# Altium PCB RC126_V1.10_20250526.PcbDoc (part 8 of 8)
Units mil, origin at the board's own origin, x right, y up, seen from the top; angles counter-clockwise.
Board outline 6299.62 x 3544.12 mil, 4 copper layers (Top, GND, Power, Bottom), stack 35.4 mil thick; 509 components, 417 nets, 1867 pads, 2150 vias.
Unrouted connection lines stored in the file: 1451.
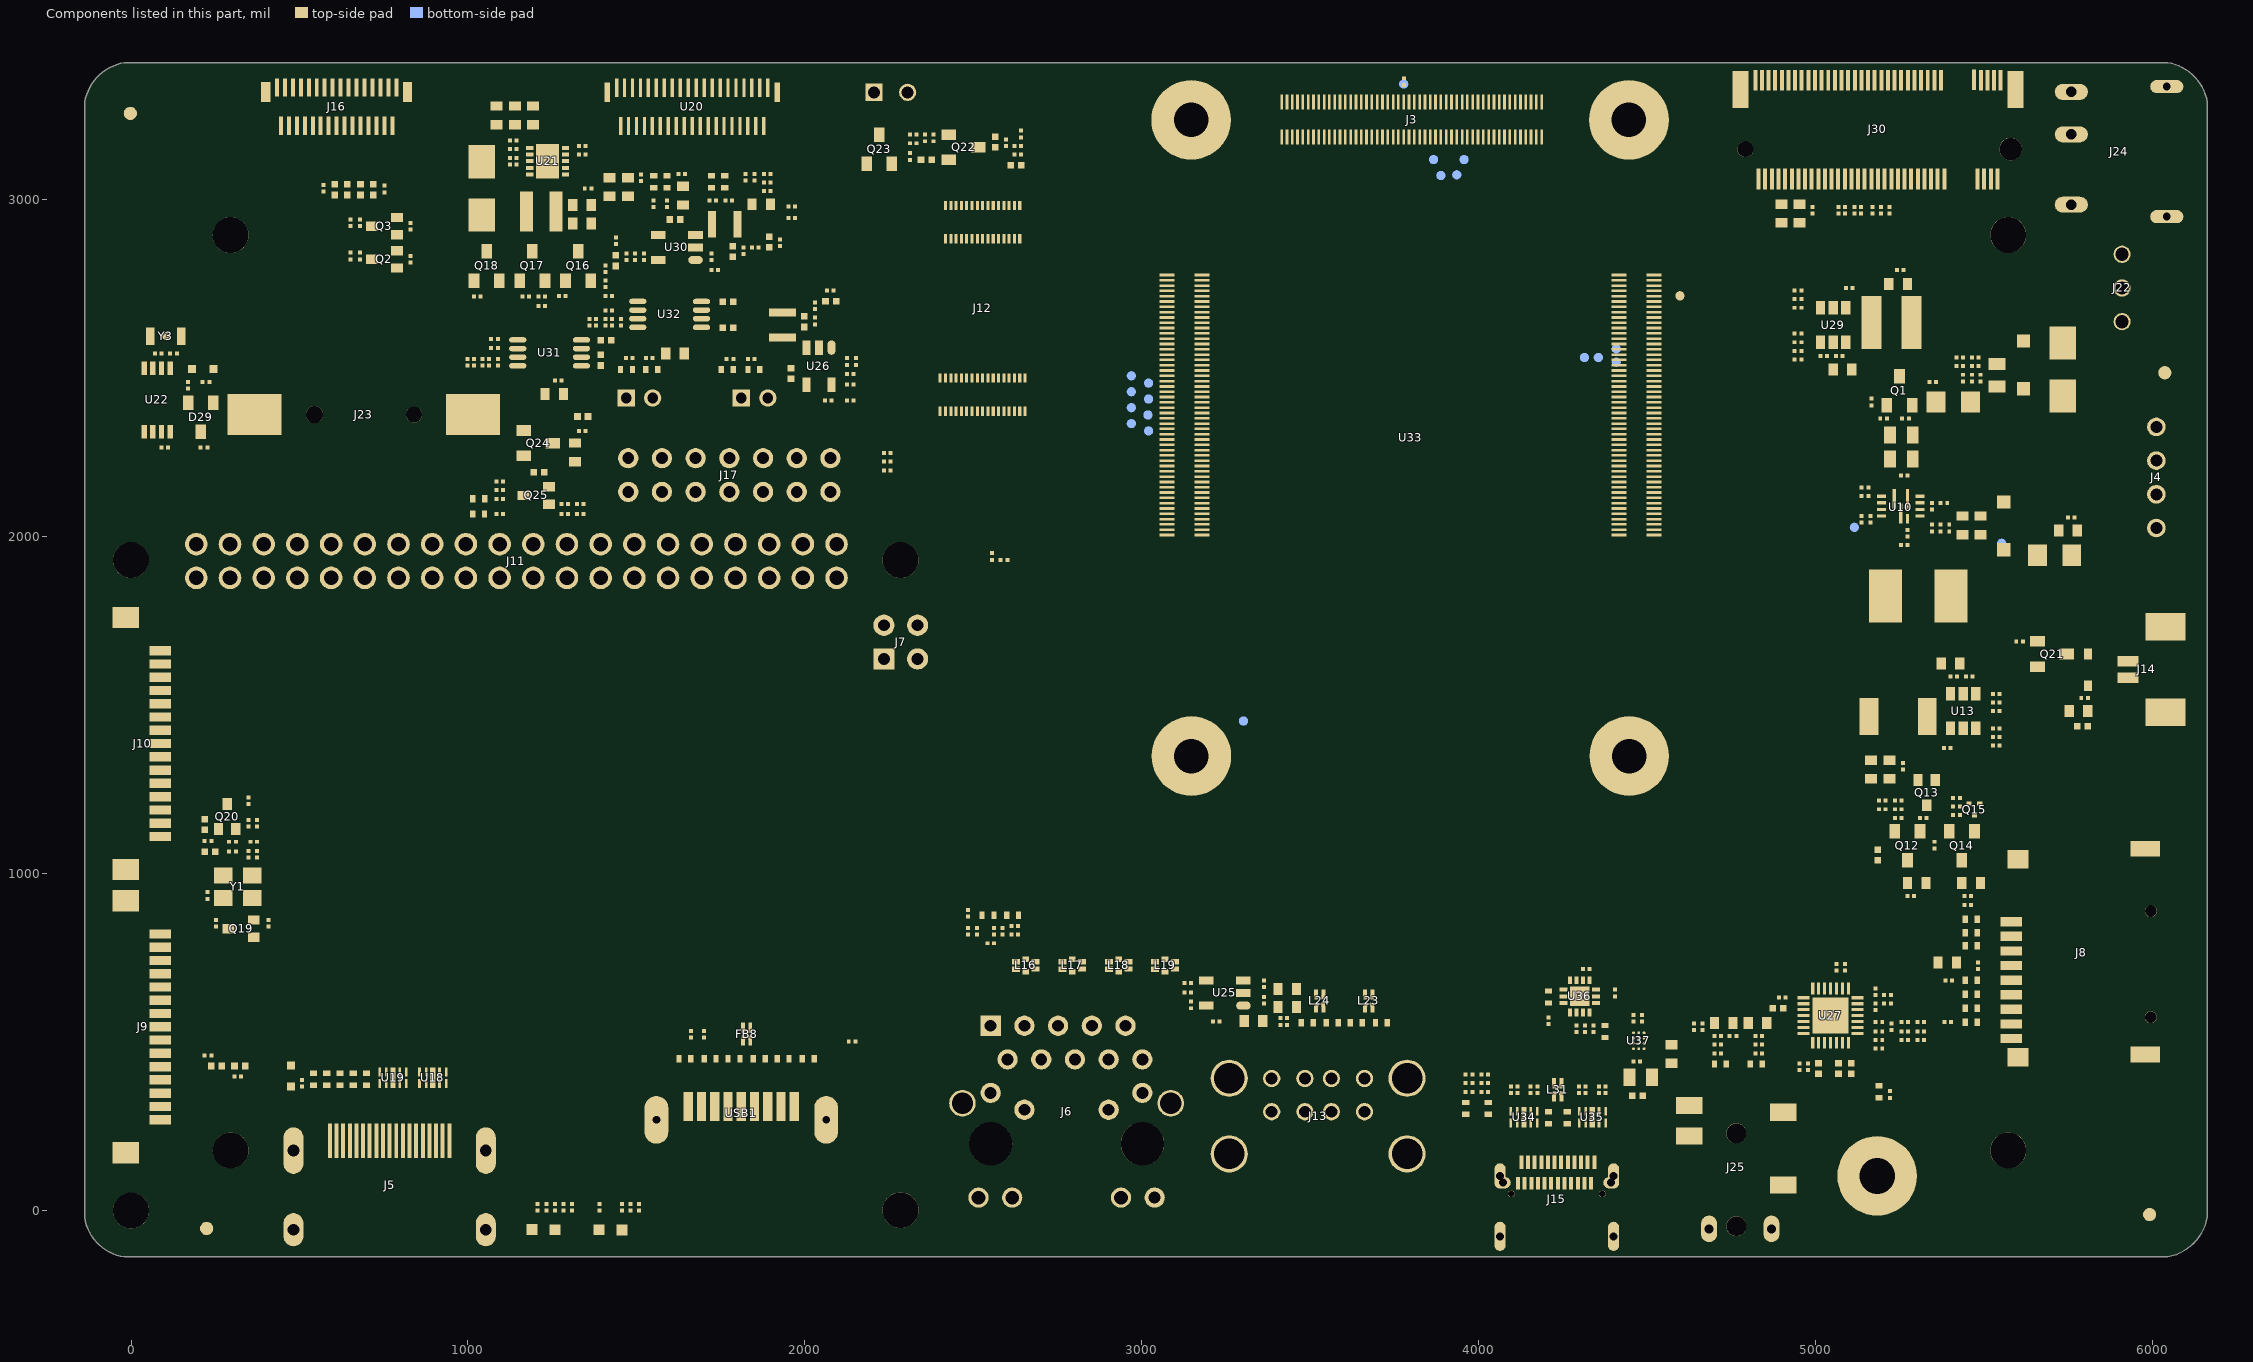
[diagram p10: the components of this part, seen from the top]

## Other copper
Top:
  region net VCC5V: 5732.28,1911.42 6039.37,1911.42 6039.37,2064.96 5761.81,2064.96 5761.81,2007.87 5732.28,1978.35 5732.28,1911.42
  region net +5V_INPUT: 4547.24,2685.04 4547.24,2600.39 4665.35,2600.39 4665.35,2685.04 4547.24,2685.04
  region net 5V_USB_HOST: 3417.32,586.61 3417.32,677.17 3379.92,677.17 3379.92,586.61 3417.32,586.61
  region net N37314100: 2039.37,2643.7 2039.37,2681.1 1889.76,2681.1 1889.76,2643.7 2039.37,2643.7
  region net VCC_UFS1V2_S0_P: 1848.43,2852.36 1848.43,2883.86 1816.93,2883.86 1816.93,2966.54 1775.59,2966.54 1775.59,2852.36 1848.43,2852.36
  region net +5V_INPUT: 1421.26,2948.82 1350.39,2948.82 1350.39,2909.45 1395.67,2909.45 1421.26,2935.04 1421.26,2948.82
  region net VCC12V: 6039.37,2354.33 5391.73,2354.33 5385.83,2360.24 5385.83,2431.1 5269.68,2431.1 5269.68,2269.69 6039.37,2269.69 6039.37,2354.33
  region net +5V_INPUT: 5685.04,1891.73 5685.04,2021.65 5338.58,2021.65 5338.58,1744.09 5456.69,1744.09 5456.69,1879.92 5468.5,1891.73 5685.04,1891.73
  region net N38162991: 5667.32,2712.6 5667.32,2525.59 5793.31,2525.59 5793.31,2712.6 5667.32,2712.6
  region net N19463943: 5074.8,2553.15 5194.88,2553.15 5196.85,2555.12 5196.85,2718.5 5127.95,2718.5 5127.95,2616.14 5114.17,2602.36 5074.8,2602.36 5074.8,2553.15
  region net +5V_INPUT: 1608.27,2950.79 1543.31,2950.79 1543.31,2883.86 1608.27,2883.86 1608.27,2950.79
  region net +5V_INPUT: 1124.02,2236.22 1124.02,2181.1 1204.72,2181.1 1204.72,2255.91 1143.7,2255.91 1124.02,2236.22
  region net VBUS_TYPEC0: 4413.39,411.42 4462.6,411.42 4462.6,466.54 4444.88,466.54 4444.88,515.75 4413.39,515.75 4413.39,411.42
  region net 5V_S0: 1230.32,2261.81 1334.65,2261.81 1334.65,2366.14 1230.32,2366.14 1230.32,2261.81
  region net N38162991: 5706.69,3372.05 5706.69,3273.62 5952.76,3273.62 5952.76,3372.05 5706.69,3372.05
  region net 5V_USB_HOST: 3417.32,562.99 3342.52,562.99 3342.52,263.78 3417.32,263.78 3417.32,562.99
  region net N19591855: 1001.97,2903.54 1192.91,2903.54 1192.91,3098.43 1169.29,3098.43 1131.89,3061.02 1131.89,3013.78 1124.02,3005.91 1001.97,3005.91 1001.97,2903.54
  region net 5V_USB_HOST: 3279.53,620.08 3279.53,588.58 3326.77,588.58 3342.52,572.83 3342.52,559.06 3417.32,559.06 3417.32,620.08 3279.53,620.08
  region net +5V_INPUT: 4312.99,570.87 4281.5,570.87 4263.78,553.15 4263.78,543.31 4320.87,543.31 4320.87,562.99 4312.99,570.87
  region net 5V_USB_HOST: 1679.13,352.36 1679.13,194.88 1706.69,194.88 1706.69,352.36 1679.13,352.36
  region net VBUS_TYPEC0: 4464.57,442.91 4413.39,442.91 4413.39,232.28 4464.57,232.28 4464.57,442.91
  region net N37314098: 1891.73,2602.36 1891.73,2578.74 1952.76,2578.74 1992.13,2539.37 2015.75,2539.37 2015.75,2582.68 1996.06,2602.36 1891.73,2602.36
  region net N38162882: 5413.39,1513.78 5413.39,1559.06 5322.83,1559.06 5301.18,1537.4 5301.18,1403.54 5364.17,1403.54 5364.17,1505.91 5372.05,1513.78 5413.39,1513.78
  region net +5V_INPUT: 1948.82,2480.32 1948.82,2419.29 2015.75,2419.29 2015.75,2480.32 1948.82,2480.32
  region net VCC3V3_SYS: 1080.71,1608.27 1080.71,1574.8 1120.08,1574.8 1120.08,1608.27 1080.71,1608.27
  region net +5V_INPUT: 4598.43,401.57 4645.67,401.57 4651.57,407.48 4651.57,515.75 4503.94,515.75 4503.94,476.38 4525.59,476.38 4535.43,466.54 4588.58,466.54 4598.43,456.69 4598.43,401.57
  region net N38163182: 5246.06,2098.43 5246.06,2059.06 5155.51,1968.5 5155.51,1744.09 5257.87,1744.09 5257.87,2098.43 5246.06,2098.43
  region net VCC12V: 5283.46,2082.68 5283.46,2127.95 5291.34,2135.83 5366.14,2135.83 5377.95,2147.64 5377.95,2350.39 5285.43,2350.39 5265.75,2330.71 5265.75,2082.68 5283.46,2082.68
  region net 3V3_PCIE: 5533.46,3108.27 5533.46,3015.75 5586.61,3015.75 5586.61,3108.27 5533.46,3108.27
  region net VCC3V3_SYS: 5362.2,1322.83 5362.2,1370.08 5196.85,1370.08 5187.01,1379.92 5187.01,1523.62 5122.05,1523.62 5122.05,1328.74 5127.95,1322.83 5362.2,1322.83
  region net 3V3_PCIE: 5037.4,3021.65 4820.87,3021.65 4820.87,2976.38 4824.8,2972.44 5037.4,2972.44 5037.4,3021.65
  region net VCC_UFS_S0: 2023.62,2688.98 2070.87,2688.98 2070.87,2736.22 2023.62,2736.22 2023.62,2688.98
  region net +5V_INPUT: 3137.8,606.3 3137.8,553.15 3216.54,553.15 3216.54,622.05 3179.13,622.05 3163.39,606.3 3137.8,606.3
  region net N37314178: 1651.57,2881.89 1734.25,2881.89 1738.19,2885.83 1738.19,2968.5 1700.79,2968.5 1700.79,2921.26 1688.98,2909.45 1651.57,2909.45 1651.57,2881.89
  region net +5V_INPUT: 4568.9,362.2 4476.38,362.2 4476.38,318.9 4568.9,318.9 4568.9,362.2
  region net VCC1V2_UFS_VCCQ_S0: 1856.3,2868.11 1856.3,2848.43 1952.76,2848.43 1952.76,2868.11 1856.3,2868.11
  region net LCD_3V3: 1194.88,2866.14 1194.88,2856.3 1185.04,2856.3 1185.04,2828.74 1228.35,2828.74 1246.06,2846.46 1246.06,2858.27 1238.19,2866.14 1194.88,2866.14
  region net 3V3_PCIE: 5253.94,2557.09 5326.77,2557.09 5326.77,2801.18 5253.94,2801.18 5253.94,2557.09
  region net VCC12V_DCIN: 5429.13,2466.54 5429.13,2368.11 5787.4,2368.11 5787.4,2466.54 5429.13,2466.54
  region net VCC3V3_SYS: 350.39,1649.61 350.39,1624.02 389.76,1624.02 389.76,1649.61 350.39,1649.61
  region net +5V_INPUT: 5037.4,2596.46 5037.4,2551.18 5027.56,2541.34 5027.56,2525.59 5021.65,2519.69 4978.35,2519.69 4978.35,2462.6 5064.96,2462.6 5064.96,2596.46 5037.4,2596.46
  region net N19591849: 1324.8,3029.53 1240.16,3029.53 1240.16,2903.54 1324.8,2903.54 1324.8,3029.53
  region net 5V_S0: 1216.54,2181.1 1285.43,2181.1 1285.43,2366.14 1216.54,2366.14 1216.54,2181.1
  region net N19591849: 1324.8,2996.06 1324.8,3003.94 1332.68,3011.81 1352.36,3011.81 1352.36,3076.77 1330.71,3098.43 1279.53,3098.43 1279.53,3088.58 1305.12,3088.58 1311.02,3082.68 1311.02,3057.09 1305.12,3051.18 1255.91,3051.18 1240.16,3035.43 1240.16,2996.06 1324.8,2996.06
  region net +5V_INPUT: 5450.79,1513.78 5450.79,1594.49 5458.66,1602.36 5545.28,1602.36 5545.28,1645.67 5413.39,1645.67 5413.39,1574.8 5423.23,1564.96 5423.23,1513.78 5450.79,1513.78
  region net VCC_LEDA2: 1409.45,3190.94 1458.66,3190.94 1458.66,3271.65 1448.82,3281.5 1448.82,3360.24 1435.04,3360.24 1435.04,3285.43 1409.45,3259.84 1409.45,3190.94
  region net VCC_LEDA2: 1001.97,3062.99 1080.71,3062.99 1080.71,3153.54 1106.3,3179.13 1106.3,3240.16 1070.87,3240.16 1001.97,3171.26 1001.97,3062.99
Power:
  region net TR1: 1562.99,1248.03 1562.99,1204.72 1598.43,1204.72 1598.43,1248.03 1562.99,1248.03
  region net TR0: 1673.23,1244.09 1643.7,1244.09 1643.7,1157.48 1673.23,1157.48 1673.23,1244.09
  region net TR0: 1647.64,1244.09 1620.08,1244.09 1620.08,1181.1 1647.64,1181.1 1647.64,1244.09
  region net N38162991: 5952.76,3279.53 5952.76,3354.33 5704.72,3354.33 5704.72,3279.53 5952.76,3279.53
  region net TR2: 1748.03,1226.38 1704.72,1226.38 1704.72,1171.26 1748.03,1171.26 1748.03,1226.38
  region net TR3: 1838.58,1208.66 1763.78,1208.66 1763.78,1179.13 1838.58,1104.33 1838.58,1208.66
Bottom:
  region net VCC_LEDK2: 1159.45,3212.6 1159.45,3188.98 1246.06,3188.98 1246.06,3212.6 1159.45,3212.6
  region net VCC_LEDA2: 1141.73,3242.13 1066.93,3242.13 1066.93,3165.35 1141.73,3165.35 1141.73,3242.13
  region net +5V_INPUT: 5673.23,2021.65 5437.01,2021.65 5437.01,1602.36 5673.23,1602.36 5673.23,2021.65
  region net LCD_3V3: 1250,2868.11 1220.47,2868.11 1206.69,2854.33 1206.69,2838.58 1214.57,2830.71 1226.38,2830.71 1245.08,2849.41 1245.08,2864.17 1250,2864.17 1250,2868.11
  region net VCC3V3_SYS: 5267.72,1322.83 5377.95,1322.83 5377.95,1360.24 5267.72,1360.24 5267.72,1322.83
  region net VCC_LEDA2: 1401.57,3261.81 1401.57,3206.69 1446.85,3206.69 1446.85,3261.81 1401.57,3261.81
  region net VCC_LEDK2: 1442.91,3161.42 1442.91,3137.8 1476.38,3137.8 1476.38,3161.42 1442.91,3161.42
  region net VCC5V: 5913.39,1984.25 5789.37,1984.25 5789.37,1913.39 5913.39,1913.39 5913.39,1984.25

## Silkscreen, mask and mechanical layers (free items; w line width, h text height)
Silkscreen Top:
  drawing of 39806 lines, arcs and shapes, not listed
  text "99" at 3399.6,3335.2 h19.68
  text "1" at 4180.6,3330.4 h19.68
  text "UFS BOOT" at 2159.45,3232.28 h23.62
  text "M KEY" at 4692.91,3157.48 h23.62 r90
  text "100" at 3374.9,3124.6 h19.68
  text "MIPI_LCD" at 1588.58,3120.08 h23.62
  text "Camero_3" at 511.81,3114.17 h23.62
  text "Connector_3" at 3653.54,3104.33 h23.62
  text "2" at 4177.4,3102.9 h19.68
  text "J12-1" at 2704,3053.5 h23.62
  text "DC_12V IN" at 5708.66,2899.61 h23.62
  text "Power_Key" at 5972.44,2791.34 h20
  text "99" at 4576.77,2773.62 h19.68 r90
  text "199" at 3238.19,2771.65 h19.68 r90
  text "200" at 3047.24,2769.69 h19.68 r90
  text "100" at 4374.02,2769.69 h19.68 r90
  text "UFS Module Only" at 2212.6,2545.28 h23.62 r90
  text "+" at 318.9,2500 h39.37
  text "12V" at 5803.15,2303.15 h23.62
  text "RECOVERY" at 1395.67,2297.24 h23.62
  text "Maskrom" at 1990.16,2291.34 h23.62
  text "Connector_1" at 4352.36,2257.87 h23.62 r90
  text "Connector_2" at 3285.43,2236.22 h23.62 r90
  text "J12" at 2470.4,2232.7 h23.62
  text "-" at 1013.78,2226.38 h39.37
  text "GND" at 5795.28,2212.6 h23.62
  text "GND" at 1330.71,2118.11 h23.62
  text "GND" at 5799.21,2114.17 h23.62
  text "5V" at 179.13,2047.24 h23.62
  text "5V" at 275.59,2045.28 h23.62
  text "TX" at 470.47,2045.28 h23.62
  text "RX" at 574.8,2045.28 h23.62
  text "GND" at 362.2,2043.31 h23.62
  text "5V" at 5812.99,2015.75 h23.62
  text "1" at 4576.77,2000 h19.68 r90
  text "2" at 4377.95,1996.06 h19.68 r90
  text "101" at 3236.22,1970.47 h19.68 r90
  text "102" at 3047.24,1962.6 h19.68 r90
  text "12V / 5V OUT" at 5844.49,1891.73 h23.62
  text "3.3V" at 157.48,1738.19 h23.62 r90
  text "GND" at 5812.99,1688.98 h23.62
  text "5V" at 5832.68,1525.59 h23.62
  text "POE" at 2253.94,1511.81 h23.62
  text "Camero_1" at 196.85,1344.49 h23.62 r90
  text "FAN" at 5970.47,1328.74 h23.62
  text "CM4 IO  V1.10" at 1208.66,753.94 h39.37
  text "Ethernet" at 2366.14,641.73 h23.62
  text "Camero_2" at 208.66,488.19 h23.62 r90
  text "USB 2.0" at 3789.37,482.28 h23.62
  text "USB 3.0" at 1407.48,411.42 h23.62
  text "TF" at 5828.74,385.83 h23.62
  text "HP Jack" at 4972.44,324.8 h23.62
  text "HDMI" at 1027.56,307.09 h23.62
  text "TYPEC" at 3891.73,200.79 h23.62
Assembly Drawing Top:
  drawing of 6139 lines, arcs and shapes, not listed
